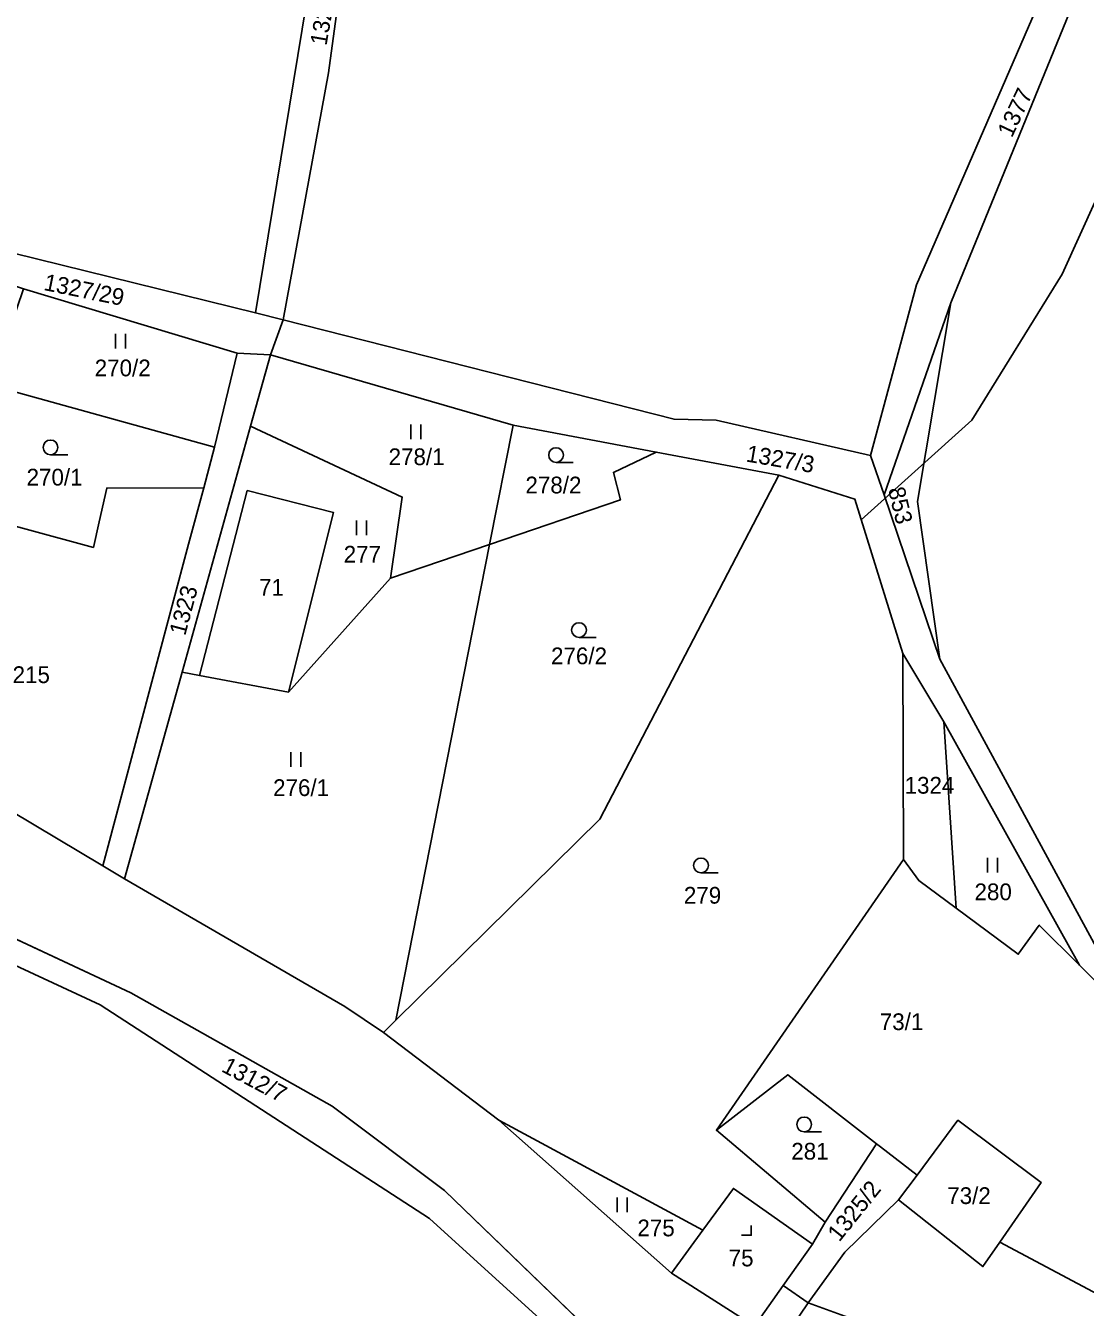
# Model space of a CAD drawing. Extents: x -588699 to -585793, y -1060280 to -1056731.
# Drawn here: x -587683.7 to -587576, y -1058227.3 to -1058097.1 of the extents above; entities that cross this region are included whole.
import ezdxf

# ---------------------------------------------------------------- set-up
doc = ezdxf.new("R2010")
doc.units = 0
for name, color, linetype in [('Druh pozemku', 7, 'Continuous'), ('Lesy', 7, 'Continuous'), ('Parcela nároku', 7, 'Continuous'), ('Vnější obvod_k šeření', 7, 'Continuous')]:
    doc.layers.add(name, color=color, linetype=linetype)

msp = doc.modelspace()

# ---------------------------------------------------------------- linework, layer by layer
at = {"layer": 'Druh pozemku'}
for p, q in [((-587674.53, -1058128.41), (-587674.53, -1058129.91)), ((-587673.51, -1058129.91), (-587673.51, -1058128.41)), ((-587644.53, -1058137.61), (-587644.53, -1058139.11)), ((-587643.51, -1058139.11), (-587643.51, -1058137.61)), ((-587679.38, -1058140.69), (-587681.13, -1058140.69)), ((-587628.03, -1058141.47), (-587629.78, -1058141.47)), ((-587650.05, -1058147.36), (-587650.05, -1058148.86)), ((-587649.03, -1058148.86), (-587649.03, -1058147.36)), ((-587625.7, -1058159.24), (-587627.45, -1058159.24)), ((-587656.72, -1058170.87), (-587656.72, -1058172.37)), ((-587655.7, -1058172.37), (-587655.7, -1058170.87)), ((-587585.96, -1058181.6), (-587585.96, -1058183.1)), ((-587584.94, -1058183.1), (-587584.94, -1058181.6)), ((-587613.31, -1058183.14), (-587615.06, -1058183.14)), ((-587602.83, -1058209.44), (-587604.58, -1058209.44)), ((-587623.57, -1058216.11), (-587623.57, -1058217.61)), ((-587622.55, -1058217.61), (-587622.55, -1058216.11))]:
    msp.add_line(p, q, dxfattribs=at)
msp.add_lwpolyline([(-587610.96, -1058219.94), (-587609.96, -1058219.94), (-587609.96, -1058218.94)], dxfattribs=at)
for centre in [(-587681.13, -1058139.94), (-587629.78, -1058140.72), (-587627.45, -1058158.49), (-587615.06, -1058182.39), (-587604.58, -1058208.69)]:
    msp.add_circle(centre, 0.75, dxfattribs=at)
at = {"layer": 'Lesy'}
for p, q in [((-587683.87, -1058123.82), (-587662.16, -1058130.38)), ((-587662.16, -1058130.38), (-587658.78, -1058130.54)), ((-587658.78, -1058130.54), (-587634.14, -1058137.67)), ((-587634.14, -1058137.67), (-587619.61, -1058140.41)), ((-587619.61, -1058140.41), (-587607.17, -1058142.76)), ((-587607.17, -1058142.76), (-587599.42, -1058145.18)), ((-587599.42, -1058145.18), (-587594.56, -1058160.86)), ((-587594.56, -1058160.86), (-587590.41, -1058167.8)), ((-587590.41, -1058167.8), (-587576.63, -1058192.51)), ((-587672.96, -1058195.32), (-587693.12, -1058185.92)), ((-587576.63, -1058192.51), (-587570.81, -1058198.31)), ((-587662.74, -1058201.08), (-587672.96, -1058195.32)), ((-587652.53, -1058206.85), (-587662.74, -1058201.08)), ((-587641.1, -1058215.41), (-587652.53, -1058206.85)), ((-587623.22, -1058232.65), (-587641.1, -1058215.41))]:
    msp.add_line(p, q, dxfattribs=at)
at = {"layer": 'Parcela nároku'}
for points in [[(-587652.91, -1058101.9), (-587657.5, -1058126.98), (-587617.79, -1058137.08), (-587613.52, -1058137.19), (-587597.84, -1058140.77), (-587593.18, -1058123.42), (-587574.98, -1058081.54), (-587563.6, -1058052.72), (-587550.81, -1058029.1), (-587550.81, -1058008.83), (-587557.43, -1057966.16), (-587581.01, -1058008.5), (-587595.41, -1058027.92), (-587609.08, -1058041.61), (-587624.52, -1058048.32), (-587647.09, -1058059.4)], [(-587527.58, -1058033.11), (-587512.43, -1058021.56), (-587484.15, -1058010.09), (-587474.8, -1058004.29), (-587465.82, -1058059.86), (-587503.14, -1058076.04), (-587532.94, -1058115.16), (-587546.85, -1058140.39), (-587566.06, -1058182.4), (-587574.29, -1058191.87), (-587590.81, -1058161.45), (-587593.08, -1058145.43), (-587589.69, -1058125.26), (-587570.64, -1058078.67), (-587551.05, -1058065.74), (-587538.76, -1058045.77)], [(-587660.3, -1058126.28), (-587654.29, -1058089.61), (-587651.15, -1058061.4), (-587647.09, -1058059.4), (-587652.91, -1058101.9), (-587657.5, -1058126.98)], [(-587666.34, -1058066.98), (-587690.45, -1058069.72), (-587696.04, -1058088.13), (-587696.51, -1058092.47), (-587698.26, -1058096.54), (-587684.71, -1058100.39), (-587689.87, -1058118.99), (-587660.3, -1058126.28), (-587654.29, -1058089.61), (-587651.15, -1058061.4)], [(-587574.98, -1058081.54), (-587570.64, -1058078.67), (-587589.69, -1058125.26), (-587596.46, -1058144.77), (-587597.84, -1058140.77), (-587593.18, -1058123.42)], [(-587689.87, -1058118.99), (-587709.77, -1058114.08), (-587710.29, -1058114.69), (-587707.09, -1058115.45), (-587688.91, -1058121.13), (-587689.21, -1058122.09), (-587683.87, -1058123.82), (-587662.16, -1058130.38), (-587658.78, -1058130.54), (-587657.5, -1058126.98), (-587660.3, -1058126.28)], [(-587687.23, -1058133.62), (-587683.87, -1058123.82), (-587662.16, -1058130.38), (-587664.46, -1058139.91)], [(-587590.81, -1058161.45), (-587593.08, -1058145.43), (-587589.69, -1058125.26), (-587596.46, -1058144.77)], [(-587667.1, -1058149.78), (-587665.56, -1058144.03), (-587664.46, -1058139.91), (-587662.16, -1058130.38), (-587658.78, -1058130.54), (-587660.8, -1058137.77), (-587667.77, -1058162.75), (-587673.63, -1058183.75), (-587675.83, -1058182.43), (-587668.76, -1058155.99)], [(-587634.14, -1058137.67), (-587658.78, -1058130.54), (-587660.8, -1058137.77), (-587645.4, -1058144.98), (-587646.6, -1058153.21), (-587636.53, -1058149.79)], [(-587664.46, -1058139.91), (-587687.23, -1058133.62), (-587690.83, -1058146.29), (-587676.77, -1058150.1), (-587676.18, -1058147.49), (-587675.41, -1058144.07), (-587665.56, -1058144.03)], [(-587645.4, -1058144.98), (-587660.8, -1058137.77), (-587667.77, -1058162.75), (-587665.99, -1058163.09), (-587661.15, -1058144.33), (-587652.38, -1058146.55), (-587656.97, -1058164.79), (-587646.6, -1058153.21)], [(-587634.14, -1058137.67), (-587619.61, -1058140.41), (-587623.96, -1058142.48), (-587623.22, -1058145.26), (-587636.53, -1058149.79)], [(-587646.07, -1058198.09), (-587636.53, -1058149.79), (-587623.22, -1058145.26), (-587623.96, -1058142.48), (-587619.61, -1058140.41), (-587607.17, -1058142.76), (-587625.35, -1058177.7)], [(-587625.35, -1058177.7), (-587607.17, -1058142.76), (-587599.42, -1058145.18), (-587594.56, -1058160.86), (-587594.49, -1058181.8), (-587613.49, -1058209.28), (-587602.44, -1058218.6), (-587603.75, -1058220.86), (-587611.76, -1058215.19), (-587614.87, -1058219.44), (-587635.6, -1058208.26), (-587647.29, -1058199.37), (-587646.07, -1058198.09)], [(-587676.77, -1058150.1), (-587676.18, -1058147.49), (-587675.41, -1058144.07), (-587665.56, -1058144.03), (-587667.1, -1058149.78), (-587668.76, -1058155.99), (-587675.83, -1058182.43), (-587699.03, -1058168.58), (-587690.83, -1058146.29)], [(-587661.15, -1058144.33), (-587665.99, -1058163.09), (-587656.97, -1058164.79), (-587652.38, -1058146.55)], [(-587656.97, -1058164.79), (-587665.99, -1058163.09), (-587667.77, -1058162.75), (-587673.63, -1058183.75), (-587651.25, -1058196.73), (-587647.29, -1058199.37), (-587646.07, -1058198.09), (-587636.53, -1058149.79), (-587646.6, -1058153.21)], [(-587590.41, -1058167.8), (-587594.56, -1058160.86), (-587594.49, -1058181.8), (-587592.95, -1058183.93), (-587589.15, -1058186.74)], [(-587576.63, -1058192.51), (-587590.41, -1058167.8), (-587589.15, -1058186.74), (-587582.84, -1058191.41), (-587580.71, -1058188.44)], [(-587641.1, -1058215.41), (-587623.22, -1058232.65), (-587626.75, -1058230.81), (-587631.42, -1058228.44), (-587642.62, -1058218.23), (-587676.1, -1058196.56), (-587686.68, -1058191.64), (-587699.23, -1058186.88), (-587706.46, -1058185.75), (-587711.77, -1058183.47), (-587708.86, -1058179.93), (-587704.04, -1058181.62), (-587693.12, -1058185.92), (-587672.96, -1058195.32), (-587652.53, -1058206.85)], [(-587613.49, -1058209.28), (-587594.49, -1058181.8), (-587592.95, -1058183.93), (-587589.15, -1058186.74), (-587582.84, -1058191.41), (-587580.71, -1058188.44), (-587576.63, -1058192.51), (-587570.81, -1058198.31), (-587573.61, -1058203.8), (-587564.72, -1058210.02), (-587574.71, -1058225.95), (-587584.71, -1058220.65), (-587580.51, -1058214.58), (-587588.96, -1058208.27), (-587593.11, -1058213.84), (-587596.84, -1058210.95), (-587597.22, -1058210.65), (-587606.24, -1058203.65)], [(-587700.35, -1058199.17), (-587701.75, -1058199.02), (-587702.14, -1058202.49), (-587708.93, -1058201.78), (-587717.53, -1058218.16), (-587729.82, -1058248.97), (-587719.99, -1058253.31), (-587674.16, -1058288.28), (-587646.41, -1058281.16), (-587640.42, -1058275.85), (-587635.5, -1058262.73), (-587628.39, -1058236.86), (-587631.42, -1058228.44), (-587642.62, -1058218.23), (-587676.1, -1058196.56), (-587686.68, -1058191.64), (-587696.89, -1058208.97), (-587701.04, -1058207.1)], [(-587597.22, -1058210.65), (-587606.24, -1058203.65), (-587613.49, -1058209.28), (-587602.44, -1058218.6)], [(-587635.6, -1058208.26), (-587614.87, -1058219.44), (-587618.05, -1058223.79)], [(-587593.11, -1058213.84), (-587594.99, -1058216.36), (-587586.42, -1058223.13), (-587584.71, -1058220.65), (-587580.51, -1058214.58), (-587588.96, -1058208.27)], [(-587564.72, -1058210.02), (-587542.68, -1058221.73), (-587533.98, -1058224.84), (-587543.81, -1058245.62), (-587594.11, -1058230.47), (-587604.18, -1058226.81), (-587600.44, -1058221.67), (-587594.99, -1058216.36), (-587586.42, -1058223.13), (-587584.71, -1058220.65), (-587574.71, -1058225.95)], [(-587606.72, -1058225.06), (-587603.75, -1058220.86), (-587602.44, -1058218.6), (-587597.22, -1058210.65), (-587596.84, -1058210.95), (-587593.11, -1058213.84), (-587594.99, -1058216.36), (-587600.44, -1058221.67), (-587604.18, -1058226.81)], [(-587618.05, -1058223.79), (-587614.87, -1058219.44), (-587611.76, -1058215.19), (-587603.75, -1058220.86), (-587606.72, -1058225.06), (-587609.63, -1058229.16)], [(-587606.72, -1058225.06), (-587609.63, -1058229.16), (-587606.63, -1058230.47), (-587604.18, -1058226.81)], [(-587604.18, -1058226.81), (-587606.63, -1058230.47), (-587596.04, -1058235.08), (-587594.11, -1058230.47)]]:
    msp.add_lwpolyline(points, close=True, dxfattribs=at)
for points in [[(-587790.12, -1058088.31), (-587777.51, -1058097.76), (-587749.47, -1058120.61), (-587748.81, -1058121.5), (-587747.87, -1058122.58), (-587725.85, -1058147.88), (-587717.98, -1058156.96), (-587705.74, -1058164.47), (-587699.03, -1058168.58), (-587675.83, -1058182.43), (-587673.63, -1058183.75), (-587651.25, -1058196.73), (-587647.29, -1058199.37), (-587635.6, -1058208.26), (-587618.05, -1058223.79), (-587609.63, -1058229.16), (-587606.63, -1058230.47), (-587596.04, -1058235.08), (-587594.11, -1058230.47), (-587543.81, -1058245.62)], [(-587546.41, -1058255.87), (-587580.84, -1058246.64), (-587593.55, -1058244.64), (-587613.43, -1058237.77), (-587623.22, -1058232.65), (-587641.1, -1058215.41), (-587652.53, -1058206.85), (-587672.96, -1058195.32), (-587693.12, -1058185.92), (-587705.33, -1058175.73), (-587706.68, -1058174.81), (-587718.79, -1058166.72), (-587720.43, -1058165.64), (-587764.02, -1058123.53), (-587773.78, -1058113.71), (-587781.14, -1058106.31), (-587794.26, -1058098.73), (-587815.92, -1058098.95), (-587829.03, -1058099.08)], [(-587570.81, -1058198.31), (-587576.63, -1058192.51), (-587590.41, -1058167.8), (-587594.56, -1058160.86), (-587599.42, -1058145.18), (-587607.17, -1058142.76), (-587619.61, -1058140.41), (-587634.14, -1058137.67), (-587658.78, -1058130.54), (-587657.5, -1058126.98), (-587617.79, -1058137.08), (-587613.52, -1058137.19), (-587597.84, -1058140.77), (-587596.46, -1058144.77), (-587590.81, -1058161.45), (-587574.29, -1058191.87)]]:
    msp.add_lwpolyline(points, dxfattribs=at)
at = {"layer": 'Vnější obvod_k šeření'}
msp.add_lwpolyline([(-587598.78, -1058147.31), (-587587.54, -1058137.18), (-587578.39, -1058122.34), (-587562.78, -1058087.91), (-587557.09, -1058081.9), (-587547.48, -1058078.1), (-587531.42, -1058078.42), (-587519.59, -1058074.95), (-587509.13, -1058065.73), (-587501.68, -1058061.09), (-587491.48, -1058057.56), (-587477.36, -1058055.8), (-587461.22, -1058052.2), (-587453.76, -1058048.47), (-587450.1, -1058043.17), (-587447.95, -1058035.13), (-587445.79, -1058031.73), (-587382.9, -1058022.25), (-587318.71, -1058013.6), (-587259.11, -1057994.38), (-587212.43, -1057983.28), (-587175.02, -1057974.24), (-587119.54, -1057948.26)], dxfattribs=at)

# ---------------------------------------------------------------- texts
at = {"layer": 'Parcela nároku'}
for s, rotation, p in [('1322', 80.1345, (-587653.1, -1058099.2)), ('1377', 64.6709, (-587583.49, -1058108.57)), ('1327/29', 348.5912, (-587681.9, -1058123.95)), ('1327/3', 350.1939, (-587610.56, -1058141.36)), ('853', 283.6958, (-587596.08, -1058144.18)), ('1323', 75.1276, (-587667.45, -1058159.13)), ('1312/7', 332.058, (-587663.87, -1058203.26)), ('1325/2', 51.2505, (-587601.02, -1058220.7))]:
    msp.add_text(s, height=1.7, rotation=rotation, dxfattribs=at).set_placement(p)
for s, p in [('270/2', (-587676.64, -1058132.72)), ('278/1', (-587646.79, -1058141.74)), ('270/1', (-587683.56, -1058143.81)), ('278/2', (-587632.89, -1058144.61)), ('277', (-587651.35, -1058151.64)), ('71', (-587659.95, -1058155)), ('276/2', (-587630.29, -1058161.96)), ('215', (-587684.98, -1058163.87)), ('276/1', (-587658.52, -1058175.34)), ('1324', (-587594.38, -1058175.1)), ('280', (-587587.28, -1058185.92)), ('279', (-587616.8, -1058186.27)), ('73/1', (-587596.9, -1058199.11)), ('281', (-587605.89, -1058212.26)), ('73/2', (-587590.05, -1058216.77)), ('275', (-587621.52, -1058220.05)), ('75', (-587612.25, -1058223.1))]:
    msp.add_text(s, height=1.7, dxfattribs=at).set_placement(p)

doc.saveas('drawing.dxf')
